// Mitsubishi GX Works2 project: 串联电路例程   PLC: FX1S

PROGRAM MAIN
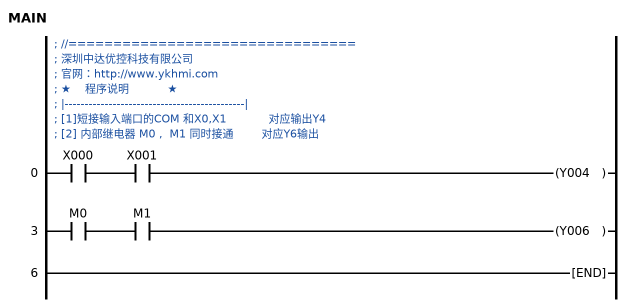
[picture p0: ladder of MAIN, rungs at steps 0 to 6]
; //================================
; 深圳中达优控科技有限公司
; 官网：http://www.ykhmi.com
; ★    程序说明           ★
; |---------------------------------------------|
; [1]短接输入端口的COM 和X0,X1            对应输出Y4
; [2] 内部继电器 M0 ,  M1 同时接通        对应Y6输出
; 
; 
; 
0     LD      X000
      AND     X001
      OUT     Y004
3     LD      M0
      AND     M1
      OUT     Y006
6     END
END_PROGRAM
